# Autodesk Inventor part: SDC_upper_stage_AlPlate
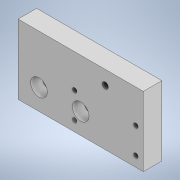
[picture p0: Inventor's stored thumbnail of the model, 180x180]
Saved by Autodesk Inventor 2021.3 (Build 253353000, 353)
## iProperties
Created: 2022-01
Part Number: SDC_upper_stage_AlPlate
Material: 一般
Document SubType Name: Modeling
Designer: kengo
Density: 1 g/cm^3
Appearance: 既定
Author: kengo
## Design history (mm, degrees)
sketch "スケッチ1"
  geometry: L1 (-78.387, 47.152)-(56.613, 47.152); L2 (56.613, 47.152)-(56.613, -27.848); L3 (56.613, -27.848)-(-78.387, -27.848); L4 (-78.387, -27.848)-(-78.387, 47.152); 1 further point
  constraints: 8 end point, 2 parallel, 1 horizontal, 1 perpendicular
  dimensions: "d0" = 135 distance of L1.start L1.end; "d1" = 75 distance of L3.end L1.start
extrude "押し出し1" new body sketch "スケッチ1" distance "d2" = 20; taper "d3" = 0 deg
sketch "スケッチ2"
  geometry: L1 (-78.387, 47.152)-(-78.387, -27.848) reference; L2 (-78.387, -27.848)-(56.613, -27.848) reference; 3 further points
  dimensions: "d4" = 45 distance of point (-10.887, -5.348) point (-55.887, -5.348); "d5" = 22.5 distance from line of L1 point (-55.887, -5.348); "d6" = 22.5 distance from line of L2 point (-55.887, -5.348); "d7" = 22.5 distance from line of L2 point (-10.887, -5.348)
hole "穴1" sketch "スケッチ2" at (-55.887, -5.348), (-10.887, -5.348) diameter "d8" = 12; stored, may be unused: countersink angle "d12" = 90 deg, drill point angle "d14" = 118 deg; dims "d9" = 16, "d10" = 18, "d11" = 12, "d13" = 22.2
sketch "スケッチ4"
  geometry: L1 (56.613, -27.848)-(56.613, 47.152) reference; L2 (-78.387, -27.848)-(56.613, -27.848) reference; 2 further points
  dimensions: "d26" = 41 distance from line of L1 point (15.613, 32.152); "d27" = 60 distance from line of L2 point (15.613, 32.152)
hole "穴3" sketch "スケッチ4" at (15.613, 32.152) diameter "d28" = 6.647; stored, may be unused: countersink angle "d32" = 90 deg, drill point angle "d34" = 118 deg; dims "d29" = 16, "d30" = 14, "d31" = 8, "d33" = 21.1
sketch "スケッチ5"
  geometry: L1 (56.613, -27.848)-(56.613, 47.152) reference; L2 (-78.387, -27.848)-(56.613, -27.848) reference; 5 further points
  dimensions: "d35" = 8 distance from line of L1 point (48.613, -16.848); "d36" = 8 distance from line of L1 point (48.613, 11.152); "d37" = 11 distance from line of L2 point (48.613, -16.848); "d38" = 28 distance of point (48.613, -16.848) point (48.613, 11.152); "d39" = 66 distance of point (48.613, 11.152) point (-17.387, 11.152); "d40" = 66 distance of point (48.613, -16.848) point (-17.387, -16.848); "d41" = 11 distance from line of L2 point (-17.387, -16.848); "d42" = 28 distance of point (-17.387, -16.848) point (-17.387, 11.152)
hole "穴4" sketch "スケッチ5" at (-17.387, 11.152), (-17.387, -16.848), (48.613, 11.152), (48.613, -16.848) diameter "d43" = 4.917; stored, may be unused: countersink angle "d47" = 90 deg, drill point angle "d49" = 118 deg; dims "d44" = 20, "d45" = 4, "d46" = 2, "d48" = 8
node "ソリッド1"
